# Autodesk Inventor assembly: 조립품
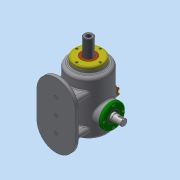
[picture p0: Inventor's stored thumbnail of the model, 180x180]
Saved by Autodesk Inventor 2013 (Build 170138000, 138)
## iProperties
Created: 2017-01
Part Number: 조립품
Document SubType Name: Assembly
Designer: dgall
Author: dgall
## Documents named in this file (16)
- C:\Users\dgall\Desktop\370107V1014\조립품.iam
- C:\Users\dgall\Desktop\370107V1014\본체.ipt
- C:\Users\dgall\Desktop\370107V1014\플레이트.ipt
- C:\Users\dgall\Desktop\370107V1014\베어링 6205.ipt
- 베어링 6205.ipt
- C:\Users\dgall\Desktop\370107V1014\축 커버-1.ipt
- C:\Users\dgall\Desktop\370107V1014\축 커버-2.ipt
- C:\Users\dgall\Desktop\370107V1014\오일실.ipt
- 오일실.ipt
- C:\Users\dgall\Desktop\370107V1014\슬라이드 커버.ipt
- C:\Users\dgall\Desktop\370107V1014\부시.ipt
- C:\Users\dgall\Desktop\370107V1014\편심축.ipt
- C:\Users\dgall\Desktop\370107V1014\슬라이드.ipt
- C:\Users\dgall\Desktop\370107V1014\볼트 M4x0.7.ipt
- C:\Users\dgall\Desktop\370107V1014\상부 캡.ipt
- C:\Users\dgall\Desktop\370107V1014\가변스프링.ipt
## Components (14 placed, 3 different names)
1. 플레이트:1
2. M4x0.7:1
3. M4x0.7:2
4. M4x0.7:3
5. M4x0.7:4
6. M4x0.7:5
7. M4x0.7:6
8. M4x0.7:7
9. M4x0.7:8
10. M4x0.7:9
11. M4x0.7:10
12. M4x0.7:11
13. M4x0.7:12
14. 가변스프링:1
